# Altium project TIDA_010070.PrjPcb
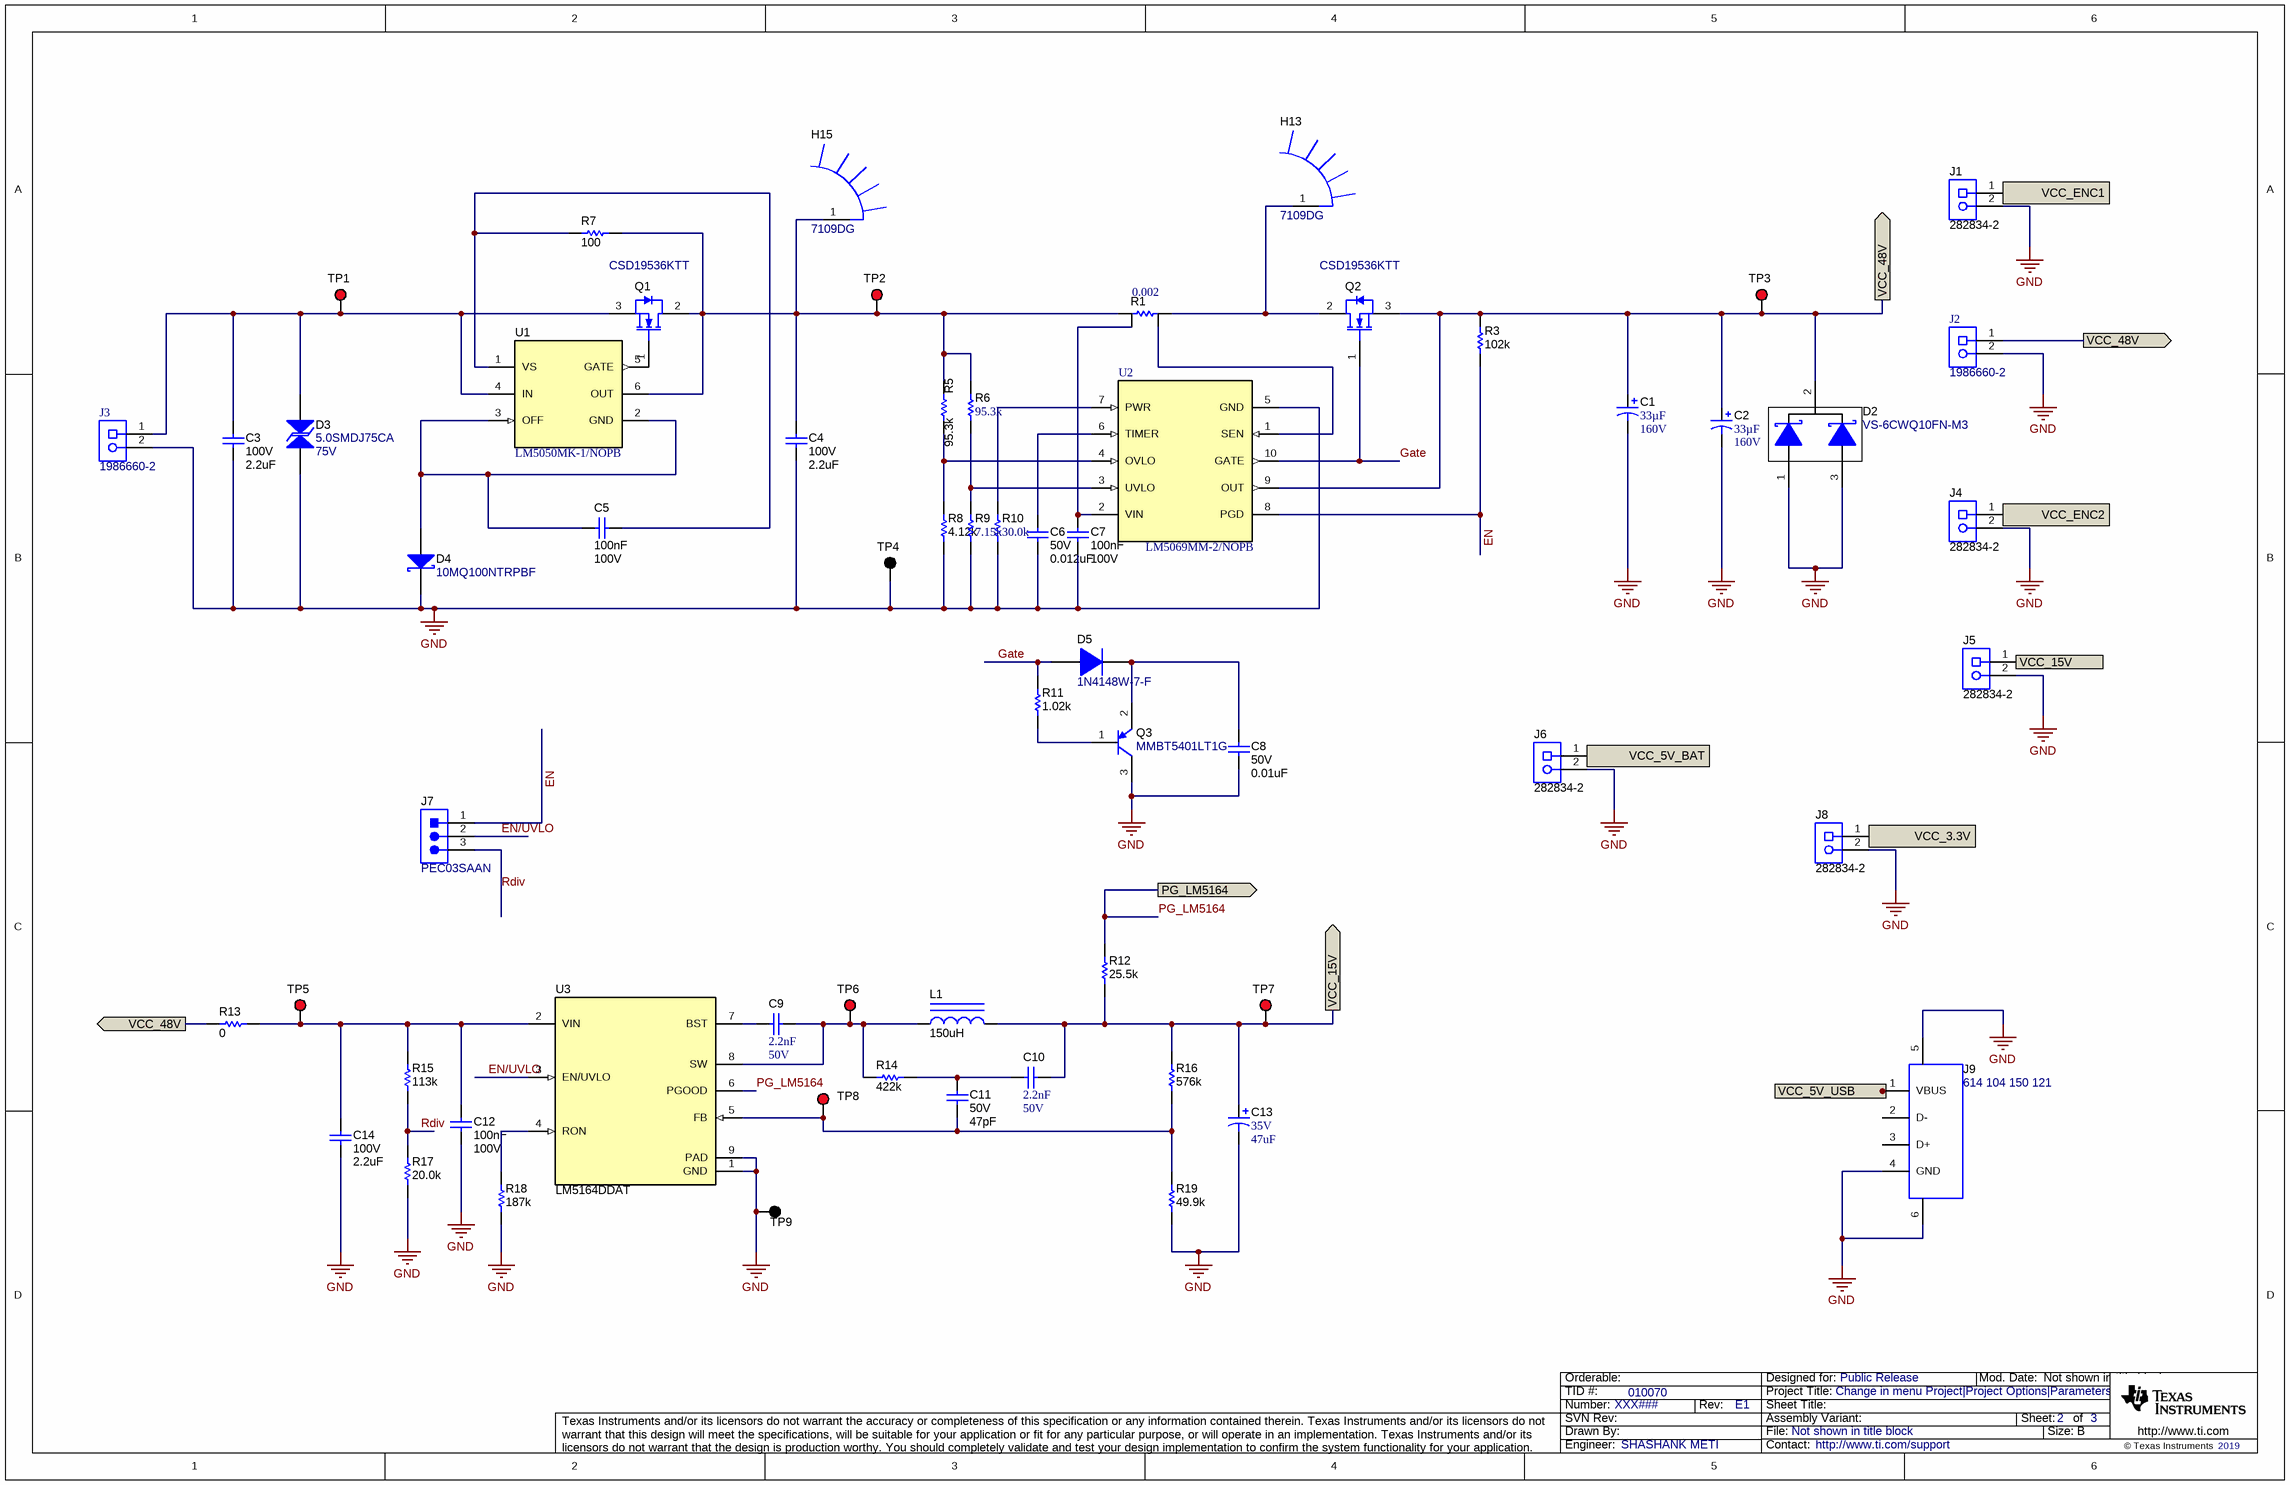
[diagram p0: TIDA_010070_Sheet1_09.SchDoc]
CopyrightYear: 2019; PCB_Layout: TESSOLVE; PCB_Rev: E1; PRJ_Customer: Public Release; PRJ_Engineer: SHASHANK METI; PRJ_Number: XXX###; PRJ_Title: Change in menu Project|Project Options|Parameters; SCH_Rev: E1; TechSupport: http://www.ti.com/support; TID: 010070
3 sheets, 149 parts. Net scope: flat (ports and power ports of the same name join across sheets).
Sheets:
  TIDA_010070_Sheet1_09.SchDoc
  TIDA_010070_Sheet2_09.SchDoc
  TIDA_010070_Hardware.SchDoc

## Sheet TIDA_010070_Sheet1_09.SchDoc
size 431 x 279 mm; Date: Not shown in title block; ApprovedBy: Not shown in title block; CheckedBy: Not shown in title block; Author: Not shown in title block; CompanyName: Not shown in title block; Engineer: Not shown in title block; Organization: Not shown in title block; Address1: Not shown in title block; Address2: Not shown in title block; Address3: Not shown in title block; Address4: Not shown in title block; DocumentNumber: 2; Revision: Use project parameter SCH_Rev; SheetNumber: 2; SheetTotal: 3; PageSetup: Record=PageOptions¦CenterHorizontal=True¦CenterVertical=True¦PrintScale=1.00¦XCorrection=1.00¦YCorrection=1.00¦PrintKind=0¦BorderSize=5000000¦LeftOffset=0¦BottomOffset=0¦Orientation=2¦PaperLength=1000¦PaperWidth=1000¦Scale=100¦PaperSource=15¦PrintQuality=600¦MediaType=1¦DitherType=10¦PaperKind=Letter¦PrintScaleMode=1

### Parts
C1  ValueDisplayed: 33µF  VDC_V: 160V  [EB_H16]  (hidden comment: EEV-EB2C330SQ)
C2  ValueDisplayed: 33µF  VDC_V: 160V  [EB_H16]  (hidden comment: EEV-EB2C330SQ)
C3  VDC_V: 100V  ValueDisplayed: 2.2uF  [1210_250]  (hidden comment: CGA6N3X7R2A225K230AB)
C4  VDC_V: 100V  ValueDisplayed: 2.2uF  [1210_250]  (hidden comment: CGA6N3X7R2A225K230AB)
C5  Cap_F: 100nF  VDC_V: 100V  [0603]  (hidden comment: HMK107B7104KAHT)
C6  VDC_V: 50V  ValueDisplayed: 0.012uF  [1206]  (hidden comment: CC1206KRX7R9BB123)
C7  Cap_F: 100nF  VDC_V: 100V  [0603]  (hidden comment: HMK107B7104KAHT)
C8  VDC_V: 50V  ValueDisplayed: 0.01uF  [1206]  (hidden comment: 12065C103KAT2A)
C9  Cap_F: 2.2nF  VDC_V: 50V  [0603]  (hidden comment: C0603C222K5RACTU)
C10  Cap_F: 2.2nF  VDC_V: 50V  [0603]  (hidden comment: C0603C222K5RACTU)
C11  VDC_V: 50V  ValueDisplayed: 47pF  [0805_HV]  (hidden comment: C0805C470J5GACTU)
C12  Cap_F: 100nF  VDC_V: 100V  [0603]  (hidden comment: HMK107B7104KAHT)
C13  VDC_V: 35V  ValueDisplayed: 47uF  [SM_RADIAL_D]  (hidden comment: EEE-FK1V470P)
C14  VDC_V: 100V  ValueDisplayed: 2.2uF  [1210_250]  (hidden comment: CGA6N3X7R2A225K230AB)
D2  VS-6CWQ10FN-M3  [DPAK]
D3  5.0SMDJ75CA  value 75V  [SMC_Bi]
D4  10MQ100NTRPBF  [SMA]
D5  1N4148W-7-F  [SOD-123]
H13  7109DG  [Aavid_7109DG]
H15  7109DG  [Aavid_7109DG]
J1  282834-2  [TEC_282834-2]
J2  1986660-2  [TE-1986660-2]
J3  1986660-2  [TE-1986660-2]
J4  282834-2  [TEC_282834-2]
J5  282834-2  [TEC_282834-2]
J6  282834-2  [TEC_282834-2]
J7  PEC03SAAN  [CONN_PEC03SAAN]
J8  282834-2  [TEC_282834-2]
J9  614 104 150 121  [WURTH_614104150121]
L1  ValueDisplayed: 150uH  [MSS1210]  (hidden comment: MSS1210-154KE)
Q1  CSD19536KTT  [KTT0002A]
Q2  CSD19536KTT  [KTT0002A]
Q3  MMBT5401LT1G  [SOT-23]
R1  ValueDisplayed: 0.002  [WSL4026_310]  (hidden comment: WSL40262L000FEB)
R3  ValueDisplayed: 102k  [0603]  (hidden comment: CRCW0603102KFKEA)
R5  value 95.3k  [0603_HV]  (hidden comment: CRCW060395K3FKEA)
R6  ValueDisplayed: 95.3k  [0603]  (hidden comment: RT0603BRD0795K3L)
R7  value 100  [0603]  (hidden comment: CRCW0603100RFKEA)
R8  ValueDisplayed: 4.12k  [0603]  (hidden comment: CRCW06034K12FKEA)
R9  ValueDisplayed: 7.15k  [0603]  (hidden comment: RG1608P-7151-B-T5)
R10  ValueDisplayed: 30.0k  [0603]  (hidden comment: RG1608P-303-B-T5)
R11  ValueDisplayed: 1.02k  [1206]  (hidden comment: RC1206FR-071K02L)
R12  ValueDisplayed: 25.5k  [0805_HV]  (hidden comment: CRCW080525K5FKEA)
R13  ValueDisplayed: 0  [5106]  (hidden comment: 5106)
R14  ValueDisplayed: 422k  [0805_HV]  (hidden comment: ERJ-6ENF4223V)
R15  ValueDisplayed: 113k  [0603]  (hidden comment: CRCW0603113KFKEA)
R16  ValueDisplayed: 576k  [0603]  (hidden comment: RC0603FR-07576KL)
R17  ValueDisplayed: 20.0k  [0603]  (hidden comment: CRCW060320K0FKEA)
R18  ValueDisplayed: 187k  [0603]  (hidden comment: CRCW0603187KFKEA)
R19  ValueDisplayed: 49.9k  [0603]  (hidden comment: RC0603FR-0749K9L)
TP1  5000  [Keystone5000]  (value not drawn)
TP2  5000  [Keystone5000]  (value not drawn)
TP3  5000  [Keystone5000]  (value not drawn)
TP4  5001  [Keystone5001]  (value not drawn)
TP5  5000  [Keystone5000]  (value not drawn)
TP6  5000  [Keystone5000]  (value not drawn)
TP7  5000  [Keystone5000]  (value not drawn)
TP8  5000  [Keystone5000]  (value not drawn)
TP9  5001  [Keystone5001]  (value not drawn)
U1  LM5050MK-1/NOPB  [DDC0006A_N]
U2  LM5069MM-2/NOPB  [DGS0010A_N]
U3  LM5164DDAT  [DDA0008E_N]

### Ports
PG_LM5164 (out), VCC_3.3V (in), VCC_5V_BAT (in), VCC_5V_USB (in), VCC_15V (out), VCC_48V (out), VCC_ENC1 (in), VCC_ENC2 (in)

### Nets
GND: C1.2(-) C2.2(-) C3.1 C4.1 C6.1 C7.2 C8.1 C12.2 C13.2(-) C14.1 D2.1(A) D2.3(A) D3.1 D4.1(K) J1.2 J2.2 J3.2 J4.2 J5.2 J6.2 J8.2 J9.4(GND) J9.5(Shield) J9.6(Shield) Q3.3(C) R8.2 R9.2 R10.1 R17.2 R18.2 R19.2 TP4.1 TP9.1 U2.5(GND) U3.1(GND) U3.9(PAD)
V_5VBAT: J6.1 ; port VCC_5V_BAT
V_P: J8.1 ; port VCC_3.3V
EN: J7.1 R3.2 U2.8(PGD)
EN/UVLO: J7.2 U3.3(EN/UVLO)
Gate: D5.2(A) Q2.1(G) R11.1 U2.10(GATE)
PG_LM5164: R12.1 U3.6(PGOOD) ; port PG_LM5164
Rdiv: J7.3 R15.2 R17.1
VCC_15V: C10.1 C13.1(+) J5.1 L1.2 R12.2 R16.1 TP7.1 ; port VCC_15V
VCC_48V: C1.1(+) C2.1(+) D2.2(K) J2.1 Q2.3(S) R3.1 R13.1 TP3.1 U2.9(OUT) ; port VCC_48V
VCC_ENC1: J1.1 ; port VCC_ENC1
VCC_ENC2: J4.1 ; port VCC_ENC2
NetC3_2: C3.2 D3.2 J3.1 Q1.3(S) TP1.1 U1.4(IN)
NetC4_2: C4.2 H15.1 Q1.2(D) R1.2 R5.2 R6.2 R7.1 TP2.1 U1.6(OUT)
NetC5_1: C5.1 R7.2 U1.1(VS)
NetC5_2: C5.2 D4.2(A) U1.2(GND) U1.3(OFF)
NetC6_2: C6.2 U2.6(TIMER)
NetC7_1: C7.1 R1.4 U2.2(VIN)
NetC8_2: C8.2 D5.1(K) Q3.2(E)
NetC9_1: C9.1 L1.1 R14.1 TP6.1 U3.8(SW)
NetC9_2: C9.2 U3.7(BST)
NetC10_2: C10.2 C11.2 R14.2
NetC11_1: C11.1 R16.2 R19.1 TP8.1 U3.5(FB)
NetC12_1: C12.1 C14.2 R13.2 R15.1 TP5.1 U3.2(VIN)
NetH13_1: H13.1 Q2.2(D) R1.1
NetQ1_1: Q1.1(G) U1.5(GATE)
NetQ3_1: Q3.1(B) R11.2
NetR1_3: R1.3 U2.1(SEN)
NetR5_1: R5.1 R8.1 U2.4(OVLO)
NetR6_1: R6.1 R9.1 U2.3(UVLO)
NetR10_2: R10.2 U2.7(PWR)
NetR18_1: R18.1 U3.4(RON)

Not connected (* = marked no-connect by the designer): J9 1(VBUS) 2(D-) 3(D+)

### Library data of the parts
C1 C2 = CMP-0860221-1: CAP, AL, 33 µF, 160 V, +/- 20%, SMD; Manufacturer: Panasonic; SizeZ_mm: 13.5; Cap_Case: 12.5x16.5mm; CompType: Capacitor; Value: 33uF; U/M: EA; TaMax_C: 105°C; TaMin_C: -55°C; SizeAreaWB_mm2: 263.5; Polarized: Y; AEC Qualified: N; IRMS_A: 4.7dA; AEC Category: Q200; SizeArea_mm2: 202.5; SizeX_mm: 15
C3 C4 C14 = CMP-0009152-2: CAP, CERM, 2.2 uF, 100 V, +/- 10%, X7R, AEC-Q200 Grade 1,; Manufacturer: TDK; TaMin_C: -55°C; ESR_ohm: 1.73m; Polarized: N; SizeAreaWB_mm2: 14.7; Value1: 0.00173 ohm; U/M: EA; Value: 2.2uF; TaMax_C: 125°C; SizeZ_mm: 2.5; SizeX_mm: 3.2; SizeArea_mm2: 8; AEC Qualified: Y; Cap_F: 2.2µF; IRMS_A: 5.59317A; AEC Grade: 1; AEC Category: Q200
C5 C7 C12 = CMP-0081011-1: CAP, CERM, 0.1 µF, 100 V,+/- 10%, X7R, AEC-Q200 Grade 1, 0603; Manufacturer: Taiyo Yuden; SizeAreaWB_mm2: 4.68; SizeArea_mm2: 1.28; AEC Qualified: Y; AEC Category: Q200; Value: 0.1uF; TaMax_C: 125°C; SizeZ_mm: 1; Polarized: N; TaMin_C: -55°C; SizeY_mm: 0.8; U/M: EA; SizeX_mm: 1.6; ValueDisplayed: 0.1µF
C6 = CMP-0008741-2: CAP, CERM, 0.012 uF, 50 V, +/- 10%, X7R, 1206; Manufacturer: Yageo America; TaMin_C: -55°C; Polarized: N; SizeAreaWB_mm2: 10.92; Value1: Unknown; U/M: EA; TaMax_C: 125°C; SizeZ_mm: 1.35; SizeX_mm: 3.2; SizeY_mm: 1.6; SizeArea_mm2: 5.12; Cap_F: 12nF; AEC Category: Q200
C8 = CMP-0008531-2: CAP, CERM, 0.01 uF, 50 V, +/- 10%, X7R, 1206; Manufacturer: AVX; TaMin_C: -55°C; ESR_ohm: 0.119; Polarized: N; SizeAreaWB_mm2: 10.92; Value1: 0.119 ohm; U/M: EA; Value: 0.01uF; TaMax_C: 125°C; SizeZ_mm: 1.35; SizeX_mm: 3.2; SizeY_mm: 1.6; SizeArea_mm2: 5.12; Cap_F: 10nF; AEC Category: Q200
C9 C10 = CMP-0006898-4: CAP, CERM, 2200 pF, 50 V, +/- 10%, X7R, 0603; Manufacturer: Kemet; TaMin_C: -55°C; Polarized: N; SizeAreaWB_mm2: 4.68; Value1: Unknown; U/M: EA; Value: 2200pF; TaMax_C: 125°C; SizeZ_mm: 1; SizeX_mm: 1.6; SizeY_mm: 0.8; SizeArea_mm2: 1.28; AEC Category: Q200
C11 = CMP-0007793-2: CAP, CERM, 47 pF, 50 V, +/- 5%, C0G/NP0, 0805; Manufacturer: Kemet; TaMin_C: -55°C; ESR_ohm: 0.115; Polarized: N; SizeAreaWB_mm2: 6.75; Value1: 0.115 ohm; U/M: EA; Value: 47pF; TaMax_C: 125°C; SizeZ_mm: 1.45; SizeX_mm: 2; SizeY_mm: 1.25; Cap_Case: 0805; SizeArea_mm2: 2.5; IRMS_A: 505mA; AEC Category: Q200
C13 = CMP-0010730-1: CAP, AL, 47 uF, 35 V, +/- 20%, 0.36 ohm, AEC-Q200 Grade 2, SMD; Manufacturer: Panasonic; TaMin_C: -55°C; ESR_ohm: 3.6d; Polarized: Y; SizeAreaWB_mm2: 84.28; U/M: EA; Value: 47uF; TaMax_C: 105°C; SizeZ_mm: 5.4; SizeX_mm: 7.8; SizeY_mm: 6.6; Cap_Case: D; SizeArea_mm2: 51.48; CompType: Capacitor; Cap_F: 47µF; IRMS_A: 2.4dA; AEC Grade: 2; AEC Category: Q200
D2 = CMP-0028773-3: Diode, Schottky, 100 V, 3.5 A, DPAK; Manufacturer: Vishay-Semiconductor; SizeX_mm: 9.91; SizeY_mm: 6.54; Io_A: 3.5A; SizeZ_mm: 2.29; Value: 100V; Green_REACh: Incomplete; AEC Category: Q101; Value2: 0.96V; AEC Qualified: N; SizeArea_mm2: 64.8114; SizeAreaWB_mm2: 101.7114; Green_Lifecycle: Not Set; RJC_CperW: 4.7; Vf_V: 960mV; TJmax_C: 150°C
D3 = CMP-0085455-1: PartNumber: SMCJ26CA-TR; Manufacturer: STMicroelectronics; RJA_CperW: 90; AEC Qualified: N; Vc: 42.1V; Vbr_Min: 28.9V; SizeY_mm: 5.9; Ppk: 1.5kW; VRWM: 26V; SizeArea_mm2: 46.846; AEC Category: Q101; SizeAreaWB_mm2: 78.526; CompType: TVS; Ipp: 37A; SizeZ_mm: 2.62; SizeX_mm: 7.94
D4 = CMP-0028354-2: Diode, Schottky, 100 V, 1.5 A, SMA; Manufacturer: International Rectifier; Green_REACh: Incomplete; SizeAreaWB_mm2: 37.3428; TJmax_C: 150°C; SizeX_mm: 5.59; Value1: 1.5A; AEC Category: Q101; Vf_V: 680mV; Vr_V: 100V; SizeY_mm: 2.92; Green_Lifecycle: Not Set; Value: 100V; SizeArea_mm2: 16.3228; Value2: 0.68V; SizeZ_mm: 2.87
D5 = CMP-0029001-2: Diode, Ultrafast, 100 V, 0.15 A, SOD-123; Manufacturer: Diodes Inc.; SizeX_mm: 3.85; Value2: 1.25V; Green_REACh: Passed; TJmax_C: 150°C; AEC Category: Q101; SizeAreaWB_mm2: 13.095; Value: 100V; Green_Lifecycle: Active; SizeY_mm: 1.7; Value1: 0.15A; SizeArea_mm2: 6.545; Io_A: 150mA; SizeZ_mm: 1.35
H13 H15 = CMP-0004038-1: Surface mount heat sink for D2PAK; Manufacturer: Aavid
J1 J4-J6 J8 = CMP-0054974-1: Terminal Block, 2x1, 2.54mm, TH; Manufacturer: TE Connectivity; CNHeader: FALSE; Green_Lifecycle: Active; Green_REACh: Passed; CT: TRUE
J2 J3 = CMP-0085661-1: Terminal Block, 2 Pos, 10.16mm, TH; Manufacturer: TE Connectivity; Cert_UL: Y; Row_Count: 1; Voltage_V: 300V; Current_A: 65A; Pitch_mm: 10.16; Gender: Female
J7 = CMP-0002338-1: Header, 100mil, 3x1, Tin, TH; Manufacturer: Sullins Connector Solutions; CNHeader: TRUE; Current_A: 3A; Green_Lifecycle: Not Set; Shrouded: N; Gender: Male; Green_REACh: Incomplete; Voltage_V: 1.8kV; Row_Count: 1; Pitch_mm: 2.54; CT: FALSE; Cert_UL: Y
J9 = CMP-0054815-1: Connector, Receptacle, USB Type A, R/A, Bottom Mount TH; Manufacturer: Wurth Elektronik; Gender: Female; CT: TRUE; CNHeader: FALSE
L1 = CMP-0061864-2: Inductor, Shielded, Ferrite, 150 uH, 2.5 A, 0.176 ohm, SMD; Manufacturer: Coilcraft; Isat: 3.4A @ 30% inductance drop; Irms: 2.5A @ 40C rise; Green_Lifecycle: Not Set; SizeAreaWB_mm2: 204.49; DCR_ohm: 0.176; Green_REACh: Incomplete; Value: 150uH; Imax_A: 2.5A; SizeZ_mm: 10; SizeX_mm: 12.3; SizeArea_mm2: 151.29; Ind_H: 150µH; AEC Category: Q200
Q1 Q2 = CMP-0000966-3: MOSFET, N-CH, 100 V, 200 A, KTT0002A (TO-263-2); Alternate Manufacturer: None; Manufacturer: Texas Instruments; SizeZ_mm: 4.7; ChType: N; Value2: 118 nC; VdsMax_V: 100V; SizeX_mm: 14.3; SizeY_mm: 10.16; Vgs_V: 20V; QgTyp_nC: 118; Value: 100V; SizeArea_mm2: 145.288; AEC Category: Q101; IdsMax_A: 200A; SizeAreaWB_mm2: 198.208
Q3 = CMP-0000333-2: Transistor, PNP, 150 V, 0.5 A, SOT-23; Manufacturer: ON Semiconductor; TaMax_C: 150°C; Value2: 240; Value1: 0.5 A; Vcesat1_V: 500mV; SizeX_mm: 2.5; SizeY_mm: 3; TaMin_C: -55°C; IcRated_A: 500mA; CompType: BJT; SizeZ_mm: 1.1; Value: 150 V; SizeArea_mm2: 7.5; NPN: 0; Vceo_V: 150V; PNP: 1; AEC Category: Q101; SizeAreaWB_mm2: 14; U/M: EA
R1 = CMP-0015295-2: RES, 0.002, 1%, 3 W, AEC-Q200 Grade 0, 4026; Manufacturer: Vishay-Dale; Power_W: 3W; TempCo: 75 ppm/C; Value_Code: 2L000; U/M: EA; Value: 0.002; Res_ohm: 2m; CompType: Resistor; AEC Qualified: Y; AEC Grade: 0; AEC Category: Q200
R3 = CMP-0021992-4: RES, 102 k, 1%, 0.1 W, AEC-Q200 Grade 0, 0603; Manufacturer: Vishay-Dale; Power_W: 100mW; TempCo: 100 ppm/C; Value: 102k; EIA_Code: E96; SizeX_mm: 1.6; SizeY_mm: 0.8; SizeZ_mm: 1; Value2: 0.1W; SizeArea_mm2: 1.28; AEC Qualified: Y; VDC_V: 75V; AEC Category: Q200; AEC Grade: 0
R5 = CRCW060395K3FKEA: RES, 95.3k ohm, 1%, 0.1W, 0603; Manufacturer: Vishay-Dale; CompType: Resistor; Res_ohm: 95300; Value_Code: 95k3; Tolerance_%: 1; Power_W: 0.1; VDC_V: 75; TempCo: 100 ppm/C; EIA_Code: E96; U/M: EA
R6 = CMP-0024540-3: RES, 95.3 k, 0.1%, 0.1 W, 0603; Manufacturer: Yageo America; Power_W: 100mW; TempCo: 25 ppm/C; Value_Code: 95k3; U/M: EA; Value: 95.3k; EIA_Code: E192; SizeX_mm: 1.6; SizeY_mm: 0.8; SizeZ_mm: 1; Value2: 0.1W; SizeArea_mm2: 1.28; VDC_V: 75V; AEC Category: Q200
R7 = CRCW0603100RFKEA: RES, 100 ohm, 1%, 0.1W, 0603; Manufacturer: Vishay-Dale; CompType: Resistor; Value_Code: 100R; Tolerance_%: 1; Power_W: 0.1; VDC_V: 75; TempCo: 100 ppm/C; EIA_Code: E96; U/M: EA
R8 = CMP-0022450-4: RES, 4.12 k, 1%, 0.1 W, AEC-Q200 Grade 0, 0603; Manufacturer: Vishay-Dale; Power_W: 100mW; TempCo: 100 ppm/C; Value_Code: 4k12; Value: 4.12k; EIA_Code: E96; SizeX_mm: 1.6; SizeY_mm: 0.8; SizeZ_mm: 1; Value2: 0.1W; SizeArea_mm2: 1.28; AEC Qualified: Y; VDC_V: 75V; AEC Category: Q200; AEC Grade: 0
R9 = CMP-0023594-3: RES, 7.15 k, 0.1%, 0.1 W, 0603; Manufacturer: Susumu Co Ltd; Power_W: 100mW; TempCo: 25 ppm/C; Value_Code: 7k15; U/M: EA; Value: 7.15k; EIA_Code: E192; SizeX_mm: 1.6; SizeY_mm: 0.8; SizeZ_mm: 1; Value2: 0.1W; SizeArea_mm2: 1.28; VDC_V: 75V; AEC Category: Q200
R10 = CMP-0023508-3: RES, 30.0 k, 0.1%, 0.1 W, 0603; Manufacturer: Susumu Co Ltd; Power_W: 100mW; TempCo: 25 ppm/C; Value_Code: 30k0; U/M: EA; Value: 30.0k; Res_ohm: 30k; SizeX_mm: 1.6; SizeY_mm: 0.8; SizeZ_mm: 1; Value2: 0.1W; SizeArea_mm2: 1.28; VDC_V: 75V; AEC Category: Q200
R11 = CMP-0017964-2: RES, 1.02 k, 1%, 0.25 W, 1206; Manufacturer: Yageo America; Power_W: 250mW; TempCo: 100 ppm/C; Value_Code: 1k02; U/M: EA; Value: 1.02k; EIA_Code: E96; SizeX_mm: 3.2; SizeY_mm: 1.6; SizeZ_mm: 1.35; Value2: 0.25W; SizeArea_mm2: 5.12; VDC_V: 200V; AEC Category: Q200
R12 = CMP-0021080-3: RES, 25.5 k, 1%, 0.125 W, AEC-Q200 Grade 0, 0805; Manufacturer: Vishay-Dale; Power_W: 125mW; TempCo: 100 ppm/C; Value_Code: 25k5; Value: 25.5k; EIA_Code: E96; SizeX_mm: 2; SizeY_mm: 1.25; SizeZ_mm: 1.45; Value2: 0.125W; SizeArea_mm2: 2.5; AEC Qualified: Y; VDC_V: 150V; AEC Category: Q200; AEC Grade: 0
R13 = CMP-0020833-2: RES, 0, 1%, 0.5 W, 0805; Manufacturer: Keystone; Power_W: 500mW; TempCo: ppm/C; U/M: EA; Value: 0; SizeX_mm: 2; SizeY_mm: 1.25; SizeZ_mm: 0.84; Value2: 0.5W; SizeArea_mm2: 2.5; AEC Qualified: N; AEC Category: Q200
R14 = CMP-0021713-3: RES, 422 k, 1%, 0.125 W, AEC-Q200 Grade 0, 0805; Manufacturer: Panasonic; Power_W: 125mW; TempCo: 100 ppm/C; Value: 422k; EIA_Code: E96; SizeX_mm: 2; SizeY_mm: 1.25; SizeZ_mm: 1.45; Value2: 0.125W; SizeArea_mm2: 2.5; AEC Qualified: Y; AEC Category: Q200; AEC Grade: 0; SizeAreaWB_mm2: 6.75
R15 = CMP-0022010-4: RES, 113 k, 1%, 0.1 W, AEC-Q200 Grade 0, 0603; Manufacturer: Vishay-Dale; Power_W: 100mW; TempCo: 100 ppm/C; Value: 113k; EIA_Code: E96; SizeX_mm: 1.6; SizeY_mm: 0.8; SizeZ_mm: 1; Value2: 0.1W; SizeArea_mm2: 1.28; AEC Qualified: Y; VDC_V: 75V; AEC Category: Q200; AEC Grade: 0
R16 = CMP-0023189-4: RES, 576 k, 1%, 0.1 W, 0603; Manufacturer: Yageo; Power_W: 100mW; TempCo: 100 ppm/C; Value: 576k; EIA_Code: E96; SizeX_mm: 1.6; SizeY_mm: 0.8; SizeZ_mm: 1; Value2: 0.1W; SizeArea_mm2: 1.28; AEC Qualified: N; VDC_V: 75V; AEC Category: Q200; SizeAreaWB_mm2: 4.68
R17 = CMP-0022204-4: RES, 20.0 k, 1%, 0.1 W, AEC-Q200 Grade 0, 0603; Manufacturer: Vishay-Dale; Power_W: 100mW; TempCo: 100 ppm/C; Value_Code: 20k0; Value: 20.0k; EIA_Code: E96; Res_ohm: 20k; SizeX_mm: 1.6; SizeY_mm: 0.8; SizeZ_mm: 1; Value2: 0.1W; SizeArea_mm2: 1.28; AEC Qualified: Y; VDC_V: 75V; AEC Category: Q200; AEC Grade: 0
R18 = CMP-0022095-4: RES, 187 k, 1%, 0.1 W, AEC-Q200 Grade 0, 0603; Manufacturer: Vishay-Dale; Power_W: 100mW; TempCo: 100 ppm/C; Value: 187k; EIA_Code: E96; SizeX_mm: 1.6; SizeY_mm: 0.8; SizeZ_mm: 1; Value2: 0.1W; SizeArea_mm2: 1.28; AEC Qualified: Y; VDC_V: 75V; AEC Category: Q200; AEC Grade: 0
R19 = CMP-0023142-5: RES, 49.9 k, 1%, 0.1 W, 0603; Manufacturer: Yageo; Power_W: 100mW; TempCo: 100 ppm/C; Value_Code: 49k9; Value: 49.9k; EIA_Code: E96; SizeX_mm: 1.6; SizeY_mm: 0.8; SizeZ_mm: 1; Value2: 0.1W; SizeArea_mm2: 1.28; AEC Qualified: N; VDC_V: 75V; AEC Category: Q200; SizeAreaWB_mm2: 4.68
TP1-TP3 TP5-TP8 = CMP-0055137-1: Test Point, Miniature, Red, TH; Manufacturer: Keystone; CNHeader: FALSE; Green_Lifecycle: Active; Green_REACh: Passed; ContactFinish: Silver; CT: TRUE
TP4 TP9 = CMP-0055138-1: Test Point, Miniature, Black, TH; Manufacturer: Keystone; CNHeader: FALSE; Green_Lifecycle: Active; Green_REACh: Passed; ContactFinish: Silver; CT: TRUE
U1 = CMP-0066129-2: High Side OR-ing FET Controller, DDC0006A (SOT-23-T-6); Manufacturer: Texas Instruments; SizeZ_mm: 0.87; SizeX_mm: 1.65; SizeY_mm: 2.95; SizeArea_mm2: 4.8675; CompType: IC; U/M: EA; SizeAreaWB_mm2: 10.4675
U2 = CMP-0071871-1: Positive High Voltage Hot Swap / Inrush Current Controller with Power Limiting, 10-pin MSOP, Pb-Free; Manufacturer: Texas Instruments; PackageTopMarking: ZXTT*SNBB; CompType: MiscPower; PowerWise: N
U3 = CMP-0080798-1: 100-V Low IQ Synchronous Buck Regulator, DDA0008E (SOIC-8); Alternate Manufacturer: Texas Instruments; SizeAreaWB_mm2: 57.4; SizeZ_mm: 1.7; SizeX_mm: 5; SizeY_mm: 6.2; SizeArea_mm2: 31; CompType: IC; AEC Qualified: N; AEC Category: Q200

## Sheet TIDA_010070_Sheet2_09.SchDoc
size 431 x 279 mm; Date: Not shown in title block; ApprovedBy: Not shown in title block; CheckedBy: Not shown in title block; Author: Not shown in title block; CompanyName: Not shown in title block; Engineer: Not shown in title block; Organization: Not shown in title block; Address1: Not shown in title block; Address2: Not shown in title block; Address3: Not shown in title block; Address4: Not shown in title block; DocumentNumber: 2; Revision: Use project parameter SCH_Rev; SheetNumber: 2; SheetTotal: 3; PageSetup: Record=PageOptions¦CenterHorizontal=True¦CenterVertical=True¦PrintScale=1.00¦XCorrection=1.00¦YCorrection=1.00¦PrintKind=0¦BorderSize=5000000¦LeftOffset=0¦BottomOffset=0¦Orientation=2¦PaperLength=1000¦PaperWidth=1000¦Scale=100¦PaperSource=15¦PrintQuality=600¦MediaType=1¦DitherType=10¦PaperKind=Letter¦PrintScaleMode=1
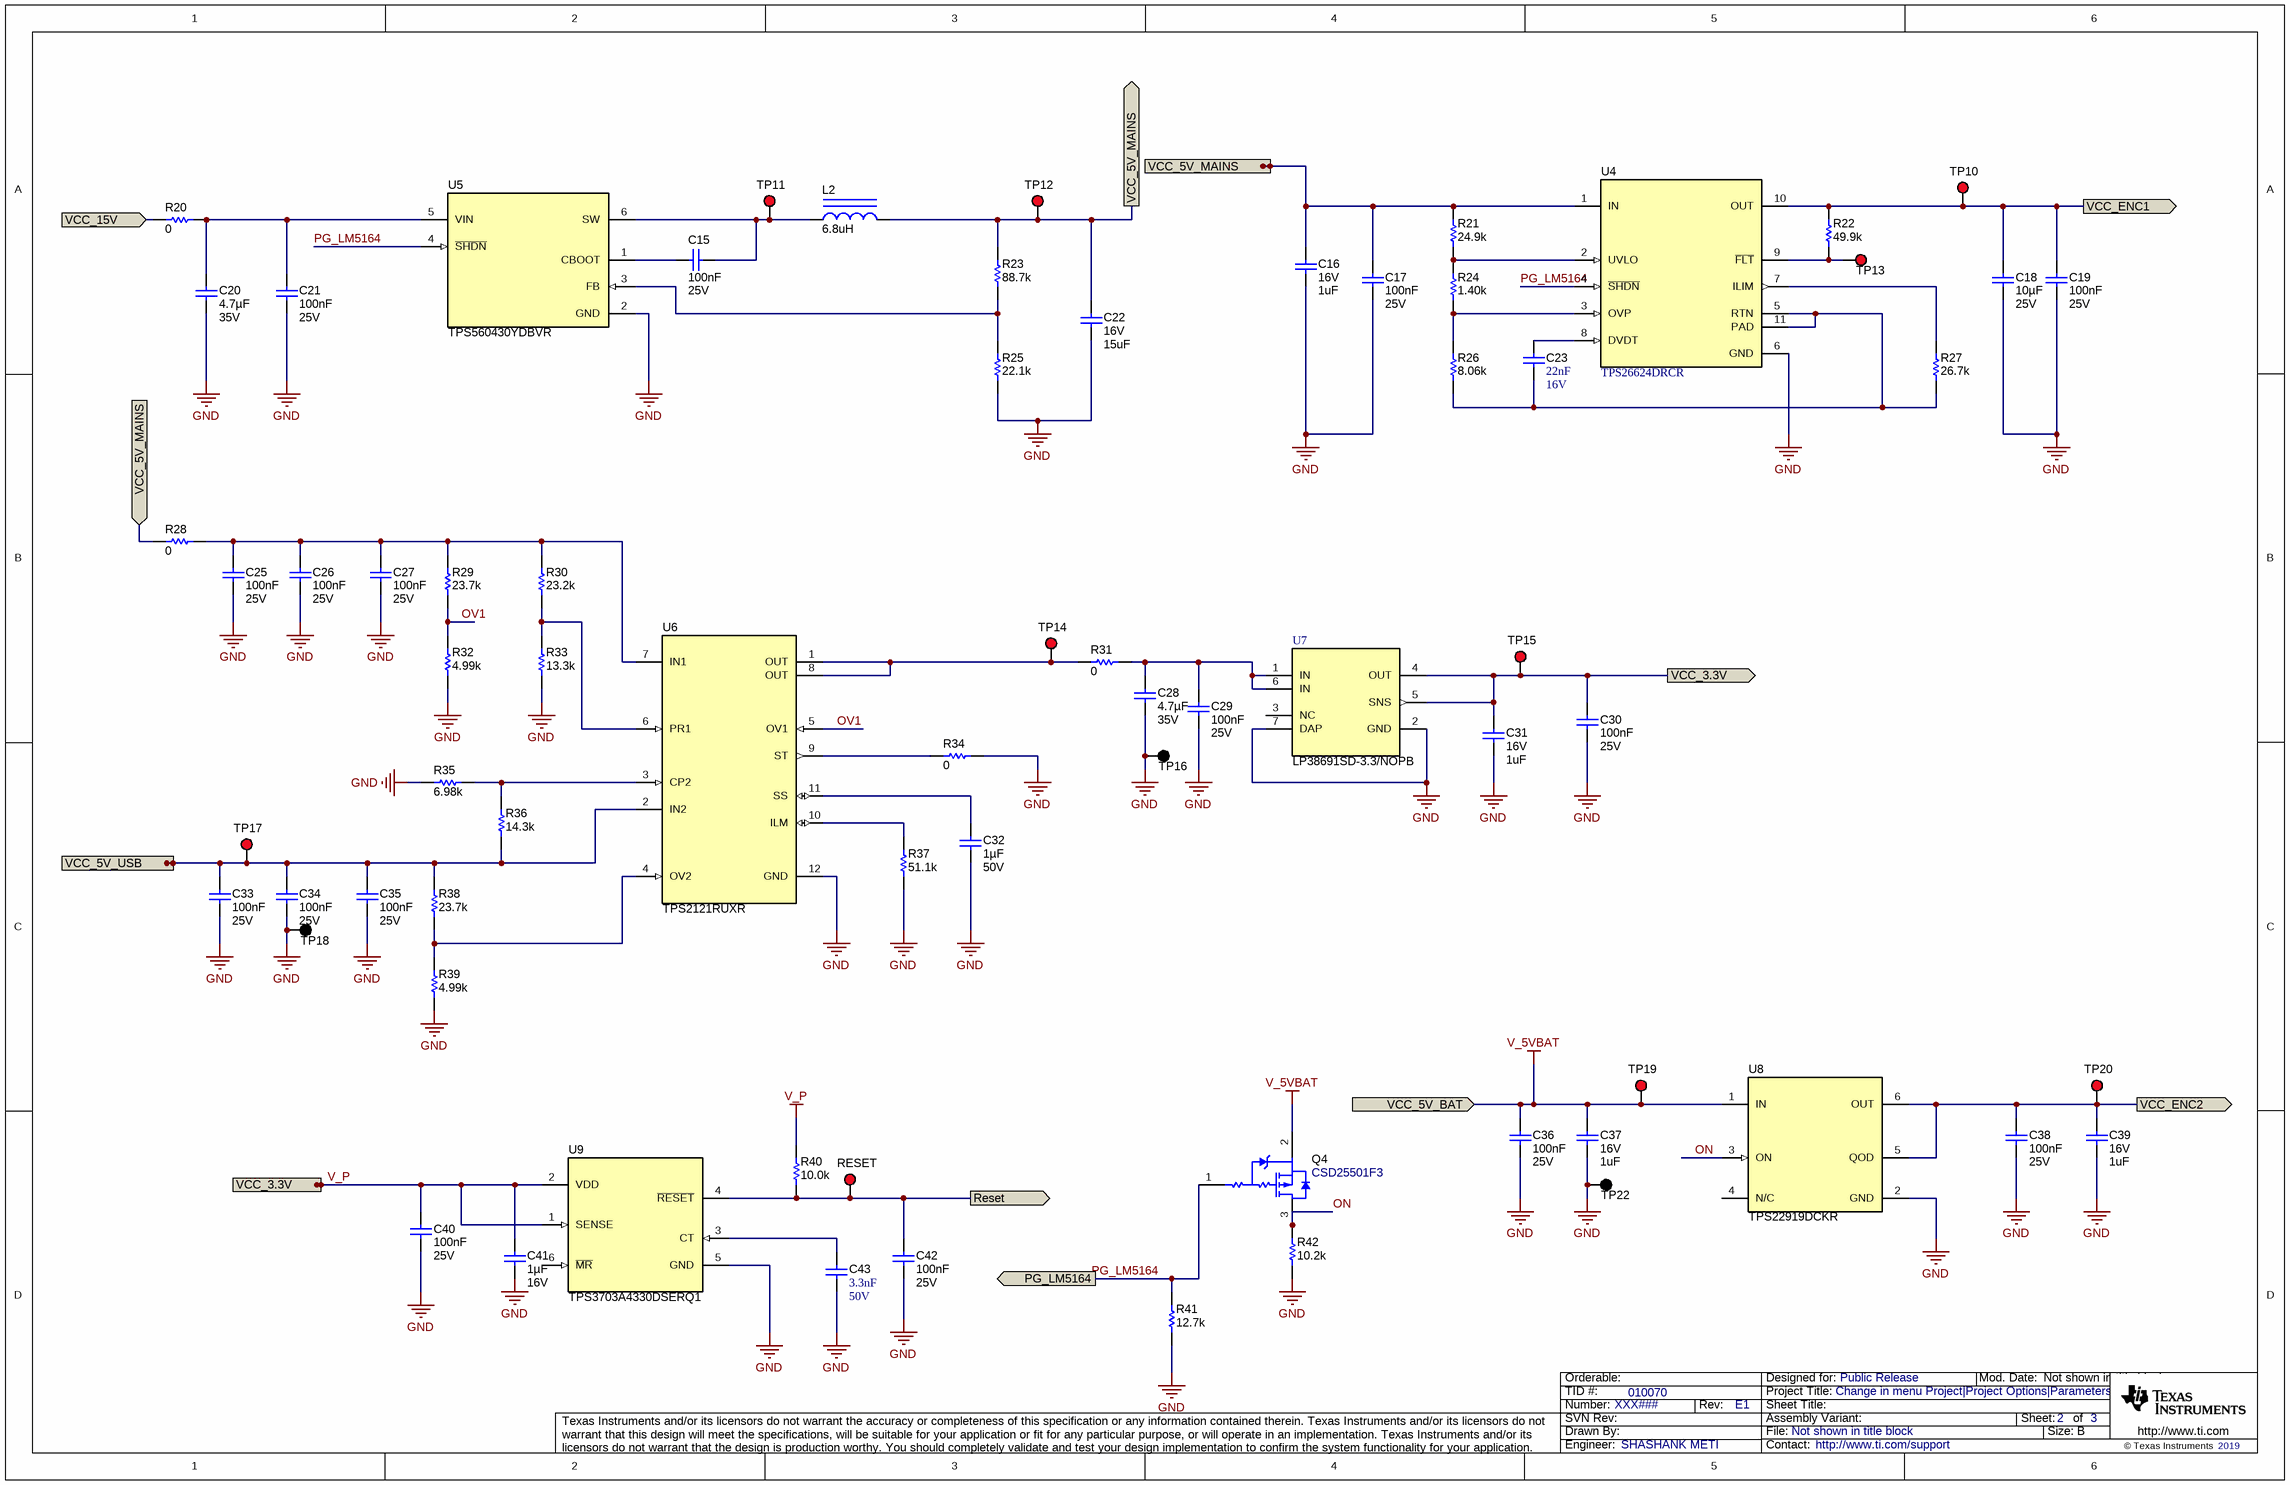
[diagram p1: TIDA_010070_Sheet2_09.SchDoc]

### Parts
C15  Cap_F: 100nF  VDC_V: 25V  [0603]  (hidden comment: 06033C104KAT2A)
C16  VDC_V: 16V  ValueDisplayed: 1uF  [0805_HV]  (hidden comment: C2012X8R1C105K125AB)
C17  Cap_F: 100nF  VDC_V: 25V  [0603]  (hidden comment: 06033C104KAT2A)
C18  Cap_F: 10µF  VDC_V: 25V  [0805_HV]  (hidden comment: GRM21BZ71E106KE15L)
C19  Cap_F: 100nF  VDC_V: 25V  [0603]  (hidden comment: 06033C104KAT2A)
C20  Cap_F: 4.7µF  VDC_V: 35V  [0805_HV]  (hidden comment: C2012X7R1V475K125AC)
C21  Cap_F: 100nF  VDC_V: 25V  [0603]  (hidden comment: 06033C104KAT2A)
C22  VDC_V: 16V  ValueDisplayed: 15uF  [1210_280]  (hidden comment: C3225X5R1C156M250AA)
C23  Cap_F: 22nF  VDC_V: 16V  [0603]  (hidden comment: C0603C223K4RACTU)
C25  Cap_F: 100nF  VDC_V: 25V  [0603]  (hidden comment: 06033C104KAT2A)
C26  Cap_F: 100nF  VDC_V: 25V  [0603]  (hidden comment: 06033C104KAT2A)
C27  Cap_F: 100nF  VDC_V: 25V  [0603]  (hidden comment: 06033C104KAT2A)
C28  Cap_F: 4.7µF  VDC_V: 35V  [0805_HV]  (hidden comment: C2012X7R1V475K125AC)
C29  Cap_F: 100nF  VDC_V: 25V  [0603]  (hidden comment: 06033C104KAT2A)
C30  Cap_F: 100nF  VDC_V: 25V  [0603]  (hidden comment: 06033C104KAT2A)
C31  VDC_V: 16V  ValueDisplayed: 1uF  [0805_HV]  (hidden comment: C2012X8R1C105K125AB)
C32  Cap_F: 1µF  VDC_V: 50V  [0805_HV]  (hidden comment: C0805C105K5RACTU)
C33  Cap_F: 100nF  VDC_V: 25V  [0603]  (hidden comment: 06033C104KAT2A)
C34  Cap_F: 100nF  VDC_V: 25V  [0603]  (hidden comment: 06033C104KAT2A)
C35  Cap_F: 100nF  VDC_V: 25V  [0603]  (hidden comment: 06033C104KAT2A)
C36  Cap_F: 100nF  VDC_V: 25V  [0603]  (hidden comment: 06033C104KAT2A)
C37  VDC_V: 16V  ValueDisplayed: 1uF  [0805_HV]  (hidden comment: C2012X8R1C105K125AB)
C38  Cap_F: 100nF  VDC_V: 25V  [0603]  (hidden comment: 06033C104KAT2A)
C39  VDC_V: 16V  ValueDisplayed: 1uF  [0805_HV]  (hidden comment: C2012X8R1C105K125AB)
C40  Cap_F: 100nF  VDC_V: 25V  [0603]  (hidden comment: 06033C104KAT2A)
C41  Cap_F: 1µF  VDC_V: 16V  [0603]  (hidden comment: GCM188R71C105KA64D)
C42  Cap_F: 100nF  VDC_V: 25V  [0603]  (hidden comment: 06033C104KAT2A)
C43  Cap_F: 3.3nF  VDC_V: 50V  [0603]  (hidden comment: C0603C332K5RACTU)
L2  ValueDisplayed: 6.8uH  [ME3220]  (hidden comment: ME3220-682MLB)
Q4  CSD25501F3  [YJN0003A]
R20  ValueDisplayed: 0  [5106]  (hidden comment: 5106)
R21  ValueDisplayed: 24.9k  [0603]  (hidden comment: CRCW060324K9FKEA)
R22  ValueDisplayed: 49.9k  [0603]  (hidden comment: CRCW060349K9FKEA)
R23  ValueDisplayed: 88.7k  [0603]  (hidden comment: CRCW060388K7FKEA)
R24  ValueDisplayed: 1.40k  [0603]  (hidden comment: CRCW06031K40FKEA)
R25  ValueDisplayed: 22.1k  [0603]  (hidden comment: CRCW060322K1FKEA)
R26  ValueDisplayed: 8.06k  [0603]  (hidden comment: CRCW06038K06FKEA)
R27  ValueDisplayed: 26.7k  [0603]  (hidden comment: CRCW060326K7FKEA)
R28  ValueDisplayed: 0  [5106]  (hidden comment: 5106)
R29  ValueDisplayed: 23.7k  [0603]  (hidden comment: CRCW060323K7FKEA)
R30  ValueDisplayed: 23.2k  [0603]  (hidden comment: CRCW060323K2FKEA)
R31  ValueDisplayed: 0  [5106]  (hidden comment: 5106)
R32  ValueDisplayed: 4.99k  [0603]  (hidden comment: CRCW06034K99FKEA)
R33  ValueDisplayed: 13.3k  [0603]  (hidden comment: CRCW060313K3FKEA)
R34  ValueDisplayed: 0  [0603]  (hidden comment: CRCW06030000Z0EA)
R35  ValueDisplayed: 6.98k  [0603]  (hidden comment: CRCW06036K98FKEA)
R36  ValueDisplayed: 14.3k  [0603]  (hidden comment: CRCW060314K3FKEA)
R37  ValueDisplayed: 51.1k  [0603]  (hidden comment: CRCW060351K1FKEA)
R38  ValueDisplayed: 23.7k  [0603]  (hidden comment: CRCW060323K7FKEA)
R39  ValueDisplayed: 4.99k  [0603]  (hidden comment: CRCW06034K99FKEA)
R40  ValueDisplayed: 10.0k  [0603]  (hidden comment: CRCW060310K0FKEA)
R41  ValueDisplayed: 12.7k  [0603]  (hidden comment: CRCW060312K7FKEA)
R42  ValueDisplayed: 10.2k  [0603]  (hidden comment: CRCW060310K2FKEA)
RESET  5000  [Keystone5000]  (value not drawn)
TP10  5000  [Keystone5000]  (value not drawn)
TP11  5000  [Keystone5000]  (value not drawn)
TP12  5000  [Keystone5000]  (value not drawn)
TP13  5000  [Keystone5000]  (value not drawn)
TP14  5000  [Keystone5000]  (value not drawn)
TP15  5000  [Keystone5000]  (value not drawn)
TP16  5001  [Keystone5001]  (value not drawn)
TP17  5000  [Keystone5000]  (value not drawn)
TP18  5001  [Keystone5001]  (value not drawn)
TP19  5000  [Keystone5000]  (value not drawn)
TP20  5000  [Keystone5000]  (value not drawn)
TP22  5001  [Keystone5001]  (value not drawn)
U4  TPS26624DRCR  [DRC0010J]
U5  TPS560430YDBVR  [DBV0006A_N]
U6  TPS2121RUXR  [RUX0012A]
U7  LP38691SD-3.3/NOPB  [NGG0006A_V]
U8  TPS22919DCKR  [DCK0006A_N]
U9  TPS3703A4330DSERQ1  [DSE0006A]

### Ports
PG_LM5164 (out), Reset (out), VCC_3.3V (in), VCC_3.3V (out), VCC_5V_BAT (in), VCC_5V_MAINS (in), VCC_5V_MAINS (out), VCC_5V_USB (in), VCC_15V (in), VCC_ENC1 (out), VCC_ENC2 (out)

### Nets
GND: C16.1 C17.2 C18.1 C19.2 C20.1 C21.1 C22.1 C25.1 C26.1 C27.1 C28.1 C29.2 C30.2 C31.1 C32.1 C33.1 C34.1 C35.1 C36.2 C37.1 C38.2 C39.1 C40.2 C41.2 C42.2 C43.2 R25.2 R32.2 R33.2 R34.2 R35.2 R37.2 R39.2 R41.2 R42.2 TP16.1 TP18.1 TP22.1 U4.6(GND) U5.2(GND) U6.12(GND) U7.2(GND) U7.7(DAP) U8.2(GND) U9.5(GND)
V_5VBAT: C36.1 C37.2 Q4.2(S) TP19.1 U8.1(IN) ; port VCC_5V_BAT
V_P: C30.1 C31.2 C40.1 C41.1 R40.2 TP15.1 U7.4(OUT) U7.5(SNS) U9.1(SENSE) U9.2(VDD) ; port VCC_3.3V
ON: Q4.3(D) R42.1 U8.3(ON)
OV1: R29.2 R32.1 U6.5(OV1)
PG_LM5164: Q4.1(G) R41.1 ; port PG_LM5164
PG_LM5164: U4.4(~{SHDN}) U5.4(~{SHDN})  [a separate net that carries the same name]
Reset: C42.1 R40.1 RESET.1 U9.4(~{RESET}) ; port Reset
VCC_5V_MAINS: C16.2 C17.1 C22.2 L2.2 R21.1 R23.1 R28.1 TP12.1 U4.1(IN) ; port VCC_5V_MAINS
VCC_5V_USB: C33.2 C34.2 C35.2 R36.2 R38.1 TP17.1 U6.2(IN2) ; port VCC_5V_USB
VCC_15V: R20.1 ; port VCC_15V
VCC_ENC1: C18.2 C19.1 R22.1 TP10.1 U4.10(OUT) ; port VCC_ENC1
VCC_ENC2: C38.1 C39.2 TP20.1 U8.5(QOD) U8.6(OUT) ; port VCC_ENC2
NetC15_1: C15.1 U5.1(CBOOT)
NetC15_2: C15.2 L2.1 TP11.1 U5.6(SW)
NetC20_2: C20.2 C21.2 R20.2 U5.5(VIN)
NetC23_1: C23.1 U4.8(DVDT)
NetC23_2: C23.2 R26.2 R27.2 U4.5(RTN) U4.11(PAD)
NetC25_2: C25.2 C26.2 C27.2 R28.2 R29.1 R30.1 U6.7(IN1)
NetC28_2: C28.2 C29.1 R31.2 U7.1(IN) U7.6(IN)
NetC32_2: C32.2 U6.11(SS)
NetC43_1: C43.1 U9.3(CT)
NetR21_2: R21.2 R24.1 U4.2(UVLO)
NetR22_2: R22.2 TP13.1 U4.9(~{FLT})
NetR23_2: R23.2 R25.1 U5.3(FB)
NetR24_2: R24.2 R26.1 U4.3(OVP)
NetR27_1: R27.1 U4.7(ILIM)
NetR30_2: R30.2 R33.1 U6.6(PR1)
NetR31_1: R31.1 TP14.1 U6.1(OUT) U6.8(OUT)
NetR34_1: R34.1 U6.9(ST)
NetR35_1: R35.1 R36.1 U6.3(CP2)
NetR37_1: R37.1 U6.10(ILM)
NetR38_2: R38.2 R39.1 U6.4(OV2)

Not connected (* = marked no-connect by the designer): U7 3(NC); U8 4(N/C); U9 6(~{MR})

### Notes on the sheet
- Labels drawn without touching a wire or pin: PG_LM5164

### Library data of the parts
C15 C17 C19 C21 C25-C27 C29 C30 C33-C36 C38 C40 C42 = CMP-0006753-4: CAP, CERM, 0.1 uF, 25 V, +/- 10%, X7R, 0603; Manufacturer: AVX; TaMin_C: -55°C; ESR_ohm: 0.05; Polarized: N; SizeAreaWB_mm2: 4.68; Value1: 0.05 ohm; U/M: EA; Value: 0.1uF; TaMax_C: 125°C; SizeZ_mm: 1; SizeX_mm: 1.6; SizeY_mm: 0.8; SizeArea_mm2: 1.28; AEC Category: Q200
C16 C31 C37 C39 = CMP-0007898-1: CAP, CERM, 1 uF, 16 V, +/- 10%, X8R, 0805; Manufacturer: TDK; TaMin_C: -55°C; Polarized: N; SizeAreaWB_mm2: 6.75; Value1: Unknown; U/M: EA; Value: 1uF; TaMax_C: 150°C; SizeZ_mm: 1.45; SizeX_mm: 2; SizeY_mm: 1.25; Cap_Case: 0805; SizeArea_mm2: 2.5; Cap_F: 1µF; AEC Category: Q200
C18 = CMP-0008378-2: CAP, CERM, 10 uF, 25 V, +/- 10%, X7R, 0805; Manufacturer: MuRata; TaMin_C: -55°C; Polarized: N; SizeAreaWB_mm2: 6.75; Value1: Unknown; U/M: EA; Value: 10uF; TaMax_C: 125°C; SizeZ_mm: 1.45; SizeX_mm: 2; SizeY_mm: 1.25; Cap_Case: 0805; SizeArea_mm2: 2.5; AEC Category: Q200
C20 C28 = CMP-0007885-2: CAP, CERM, 4.7 uF, 35 V, +/- 10%, X7R, 0805; Manufacturer: TDK; TaMin_C: -55°C; ESR_ohm: 2.346m; Polarized: N; SizeAreaWB_mm2: 6.75; Value1: 0.002346 ohm; U/M: EA; Value: 4.7uF; TaMax_C: 125°C; SizeZ_mm: 1.45; SizeX_mm: 2; SizeY_mm: 1.25; Cap_Case: 0805; SizeArea_mm2: 2.5; IRMS_A: 4.26021A; AEC Category: Q200
C22 = CMP-0009102-1: CAP, CERM, 15 uF, 16 V, +/- 20%, X5R, 1210; Manufacturer: TDK; TaMin_C: -55°C; ESR_ohm: 2.949m; Polarized: N; SizeAreaWB_mm2: 14.7; Value1: 0.002949 ohm; U/M: EA; Value: 15uF; TaMax_C: 85°C; SizeZ_mm: 2.8; SizeX_mm: 3.2; SizeY_mm: 2.5; SizeArea_mm2: 8; Cap_F: 15µF; IRMS_A: 4.28133A; AEC Category: Q200
C23 = CMP-0006900-4: CAP, CERM, 0.022 uF, 16 V, +/- 10%, X7R, 0603; Manufacturer: Kemet; TaMin_C: -55°C; Polarized: N; SizeAreaWB_mm2: 4.68; Value1: Unknown; U/M: EA; TaMax_C: 125°C; SizeZ_mm: 1; SizeX_mm: 1.6; SizeY_mm: 0.8; SizeArea_mm2: 1.28; AEC Category: Q200
C32 = CMP-0007730-2: CAP, CERM, 1 uF, 50 V, +/- 10%, X7R, 0805; Manufacturer: Kemet; TaMin_C: -55°C; Polarized: N; SizeAreaWB_mm2: 6.75; Value1: Unknown; U/M: EA; Value: 1uF; TaMax_C: 125°C; SizeZ_mm: 1.45; SizeX_mm: 2; SizeY_mm: 1.25; Cap_Case: 0805; SizeArea_mm2: 2.5; AEC Category: Q200
C41 = CMP-0007136-5: CAP, CERM, 1 uF, 16 V, +/- 10%, X7R, AEC-Q200 Grade 1, 0603; Manufacturer: MuRata; TaMin_C: -55°C; Polarized: N; SizeAreaWB_mm2: 4.68; Value1: Unknown; U/M: EA; Value: 1uF; TaMax_C: 125°C; SizeZ_mm: 1; SizeX_mm: 1.6; SizeY_mm: 0.8; SizeArea_mm2: 1.28; AEC Qualified: Y; AEC Category: Q200
C43 = CMP-0006922-4: CAP, CERM, 3300 pF, 50 V, +/- 10%, X7R, 0603; Manufacturer: Kemet; TaMin_C: -55°C; Polarized: N; SizeAreaWB_mm2: 4.68; Value1: Unknown; U/M: EA; Value: 3300pF; TaMax_C: 125°C; SizeZ_mm: 1; SizeX_mm: 1.6; SizeY_mm: 0.8; SizeArea_mm2: 1.28; AEC Category: Q200
L2 = CMP-0060543-1: Inductor, Drum Core, Ferrite, 6.8 uH, 1.1 A, 0.27 ohm, SMD; Manufacturer: Coilcraft; Isat: 1.2A @ 30% inductance drop; Irms: 1.1A @ 40C rise; Green_Lifecycle: Not Set; SizeAreaWB_mm2: 15.96; DCR_ohm: 0.27; Green_REACh: Incomplete; Value: 6.8uH; Imax_A: 1.1A; SizeZ_mm: 2; SizeX_mm: 3.2; SizeY_mm: 2.8; SizeArea_mm2: 8.96; Ind_H: 6.8µH; AEC Category: Q200
Q4 = CMP-0078322-2: MOSFET, P-CH, -20 V, -3.6 A, YJN0003A (PICOSTAR-3); Manufacturer: Texas Instruments; Alternate Manufacturer: None; SizeArea_mm2: 0.414; VdsMax_V: -20V; QgTyp_nC: 1.02; Value1: 0.076 ohm; AEC Category: Q101; SizeX_mm: 0.69; IdsMax_A: -3.6A; Value: -20V; Rdson45_ohm: 0.076; Value2: 1.02 nC; SizeAreaWB_mm2: 2.704; SizeZ_mm: 0.22; SizeY_mm: 0.6; ChType: P; AEC Qualified: N; ChMode: Enhancement
R20 R28 R31 = CMP-0020833-2: as R13 on sheet TIDA_010070_Sheet1_09
R21 = CMP-0022237-4: RES, 24.9 k, 1%, 0.1 W, AEC-Q200 Grade 0, 0603; Manufacturer: Vishay-Dale; Power_W: 100mW; TempCo: 100 ppm/C; Value_Code: 24k9; Value: 24.9k; EIA_Code: E96; SizeX_mm: 1.6; SizeY_mm: 0.8; SizeZ_mm: 1; Value2: 0.1W; SizeArea_mm2: 1.28; AEC Qualified: Y; VDC_V: 75V; AEC Category: Q200; AEC Grade: 0
R22 = CMP-0022447-4: RES, 49.9 k, 1%, 0.1 W, AEC-Q200 Grade 0, 0603; Manufacturer: Vishay-Dale; Power_W: 100mW; TempCo: 100 ppm/C; Value_Code: 49k9; Value: 49.9k; EIA_Code: E96; SizeX_mm: 1.6; SizeY_mm: 0.8; SizeZ_mm: 1; Value2: 0.1W; SizeArea_mm2: 1.28; AEC Qualified: Y; VDC_V: 75V; AEC Category: Q200; AEC Grade: 0
R23 = CMP-0022632-4: RES, 88.7 k, 1%, 0.1 W, AEC-Q200 Grade 0, 0603; Manufacturer: Vishay-Dale; Power_W: 100mW; TempCo: 100 ppm/C; Value_Code: 88k7; Value: 88.7k; EIA_Code: E96; SizeX_mm: 1.6; SizeY_mm: 0.8; SizeZ_mm: 1; Value2: 0.1W; SizeArea_mm2: 1.28; AEC Qualified: Y; VDC_V: 75V; AEC Category: Q200; AEC Grade: 0
R24 = CMP-0022123-4: RES, 1.40 k, 1%, 0.1 W, AEC-Q200 Grade 0, 0603; Manufacturer: Vishay-Dale; Power_W: 100mW; TempCo: 100 ppm/C; Value_Code: 1k40; Value: 1.40k; EIA_Code: E96; Res_ohm: 1.4k; SizeX_mm: 1.6; SizeY_mm: 0.8; SizeZ_mm: 1; Value2: 0.1W; SizeArea_mm2: 1.28; AEC Qualified: Y; VDC_V: 75V; AEC Category: Q200; AEC Grade: 0
R25 = CMP-0022220-4: RES, 22.1 k, 1%, 0.1 W, AEC-Q200 Grade 0, 0603; Manufacturer: Vishay-Dale; Power_W: 100mW; TempCo: 100 ppm/C; Value_Code: 22k1; Value: 22.1k; EIA_Code: E96; SizeX_mm: 1.6; SizeY_mm: 0.8; SizeZ_mm: 1; Value2: 0.1W; SizeArea_mm2: 1.28; AEC Qualified: Y; VDC_V: 75V; AEC Category: Q200; AEC Grade: 0
R26 = CMP-0022634-4: RES, 8.06 k, 1%, 0.1 W, AEC-Q200 Grade 0, 0603; Manufacturer: Vishay-Dale; Power_W: 100mW; TempCo: 100 ppm/C; Value_Code: 8k06; Value: 8.06k; EIA_Code: E96; SizeX_mm: 1.6; SizeY_mm: 0.8; SizeZ_mm: 1; Value2: 0.1W; SizeArea_mm2: 1.28; AEC Qualified: Y; VDC_V: 75V; AEC Category: Q200; AEC Grade: 0
R27 = CMP-0022249-4: RES, 26.7 k, 1%, 0.1 W, AEC-Q200 Grade 0, 0603; Manufacturer: Vishay-Dale; Power_W: 100mW; TempCo: 100 ppm/C; Value_Code: 26k7; Value: 26.7k; EIA_Code: E96; SizeX_mm: 1.6; SizeY_mm: 0.8; SizeZ_mm: 1; Value2: 0.1W; SizeArea_mm2: 1.28; AEC Qualified: Y; VDC_V: 75V; AEC Category: Q200; AEC Grade: 0
R29 R38 = CMP-0022229-4: RES, 23.7 k, 1%, 0.1 W, AEC-Q200 Grade 0, 0603; Manufacturer: Vishay-Dale; Power_W: 100mW; TempCo: 100 ppm/C; Value_Code: 23k7; Value: 23.7k; EIA_Code: E96; SizeX_mm: 1.6; SizeY_mm: 0.8; SizeZ_mm: 1; Value2: 0.1W; SizeArea_mm2: 1.28; AEC Qualified: Y; VDC_V: 75V; AEC Category: Q200; AEC Grade: 0
R30 = CMP-0022228-4: RES, 23.2 k, 1%, 0.1 W, AEC-Q200 Grade 0, 0603; Manufacturer: Vishay-Dale; Power_W: 100mW; TempCo: 100 ppm/C; Value_Code: 23k2; Value: 23.2k; EIA_Code: E96; SizeX_mm: 1.6; SizeY_mm: 0.8; SizeZ_mm: 1; Value2: 0.1W; SizeArea_mm2: 1.28; AEC Qualified: Y; VDC_V: 75V; AEC Category: Q200; AEC Grade: 0
R32 R39 = CMP-0022458-4: RES, 4.99 k, 1%, 0.1 W, AEC-Q200 Grade 0, 0603; Manufacturer: Vishay-Dale; Power_W: 100mW; TempCo: 100 ppm/C; Value_Code: 4k99; Value: 4.99k; EIA_Code: E96; SizeX_mm: 1.6; SizeY_mm: 0.8; SizeZ_mm: 1; Value2: 0.1W; SizeArea_mm2: 1.28; AEC Qualified: Y; VDC_V: 75V; AEC Category: Q200; AEC Grade: 0
R33 = CMP-0022043-4: RES, 13.3 k, 1%, 0.1 W, AEC-Q200 Grade 0, 0603; Manufacturer: Vishay-Dale; Power_W: 100mW; TempCo: 100 ppm/C; Value_Code: 13k3; Value: 13.3k; EIA_Code: E96; SizeX_mm: 1.6; SizeY_mm: 0.8; SizeZ_mm: 1; Value2: 0.1W; SizeArea_mm2: 1.28; AEC Qualified: Y; VDC_V: 75V; AEC Category: Q200; AEC Grade: 0
R34 = CMP-0025697-4: RES, 0, 5%, 0.1 W, AEC-Q200 Grade 0, 0603; Manufacturer: Vishay-Dale; Power_W: 100mW; TempCo: 200 ppm/C; Value_Code: 0000; Value: 0; EIA_Code: E24; SizeX_mm: 1.6; SizeY_mm: 0.8; SizeZ_mm: 1; Value2: 0.1W; SizeArea_mm2: 1.28; AEC Qualified: Y; VDC_V: 75V; AEC Category: Q200
R35 = CMP-0022564-4: RES, 6.98 k, 1%, 0.1 W, AEC-Q200 Grade 0, 0603; Manufacturer: Vishay-Dale; Power_W: 100mW; TempCo: 100 ppm/C; Value_Code: 6k98; Value: 6.98k; EIA_Code: E96; SizeX_mm: 1.6; SizeY_mm: 0.8; SizeZ_mm: 1; Value2: 0.1W; SizeArea_mm2: 1.28; AEC Qualified: Y; VDC_V: 75V; AEC Category: Q200; AEC Grade: 0
R36 = CMP-0022055-4: RES, 14.3 k, 1%, 0.1 W, AEC-Q200 Grade 0, 0603; Manufacturer: Vishay-Dale; Power_W: 100mW; TempCo: 100 ppm/C; Value_Code: 14k3; Value: 14.3k; EIA_Code: E96; SizeX_mm: 1.6; SizeY_mm: 0.8; SizeZ_mm: 1; Value2: 0.1W; SizeArea_mm2: 1.28; AEC Qualified: Y; VDC_V: 75V; AEC Category: Q200; AEC Grade: 0
R37 = CMP-0022482-4: RES, 51.1 k, 1%, 0.1 W, AEC-Q200 Grade 0, 0603; Manufacturer: Vishay-Dale; Power_W: 100mW; TempCo: 100 ppm/C; Value_Code: 51k1; Value: 51.1k; EIA_Code: E96; SizeX_mm: 1.6; SizeY_mm: 0.8; SizeZ_mm: 1; Value2: 0.1W; SizeArea_mm2: 1.28; AEC Qualified: Y; VDC_V: 75V; AEC Category: Q200; AEC Grade: 0
R40 = CMP-0021998-4: RES, 10.0 k, 1%, 0.1 W, AEC-Q200 Grade 0, 0603; Manufacturer: Vishay-Dale; Power_W: 100mW; TempCo: 100 ppm/C; Value_Code: 10k0; Value: 10.0k; EIA_Code: E96; Res_ohm: 10k; SizeX_mm: 1.6; SizeY_mm: 0.8; SizeZ_mm: 1; Value2: 0.1W; SizeArea_mm2: 1.28; AEC Qualified: Y; VDC_V: 75V; AEC Category: Q200; AEC Grade: 0
R41 = CMP-0022032-4: RES, 12.7 k, 1%, 0.1 W, AEC-Q200 Grade 0, 0603; Manufacturer: Vishay-Dale; Power_W: 100mW; TempCo: 100 ppm/C; Value_Code: 12k7; Value: 12.7k; EIA_Code: E96; SizeX_mm: 1.6; SizeY_mm: 0.8; SizeZ_mm: 1; Value2: 0.1W; SizeArea_mm2: 1.28; AEC Qualified: Y; VDC_V: 75V; AEC Category: Q200; AEC Grade: 0
R42 = CMP-0021999-4: RES, 10.2 k, 1%, 0.1 W, AEC-Q200 Grade 0, 0603; Manufacturer: Vishay-Dale; Power_W: 100mW; TempCo: 100 ppm/C; Value_Code: 10k2; Value: 10.2k; EIA_Code: E96; SizeX_mm: 1.6; SizeY_mm: 0.8; SizeZ_mm: 1; Value2: 0.1W; SizeArea_mm2: 1.28; AEC Qualified: Y; VDC_V: 75V; AEC Category: Q200; AEC Grade: 0
RESET TP10-TP15 TP17 TP19 TP20 = CMP-0055137-1: as TP1 on sheet TIDA_010070_Sheet1_09
TP16 TP18 TP22 = CMP-0055138-1: as TP4 on sheet TIDA_010070_Sheet1_09
U4 = CMP-0013390-7: 60-V, 800-mA Industrial eFuse with Integrated Reverse Polarity Protection, DRC0010J (VSON-10); Alternate PartNumber: TPS26624DRCT; Alternate Manufacturer: Texas Instruments; SizeArea_mm2: 9; AEC Category: Q200; SizeAreaWB_mm2: 16; Rating: Catalog; SizeY_mm: 3; SizeZ_mm: 1; AEC Qualified: N; CompType: IC
U5 = CMP-0065101-2: 4V to 36 V 0.6 A Synchronous Step-Down Converter, DBV0006A (SOT-23-6); Manufacturer: Texas Instruments; Alternate PartNumber: TPS560430YDBVT; SizeX_mm: 2.8; SizeY_mm: 2.9; CompType: IC; SizeZ_mm: 1.45; SizeArea_mm2: 8.12; SizeAreaWB_mm2: 14.82; U/M: EA
U6 = CMP-0078351-3: 2.7V-22V, 4A, 50mohm Priority Power MUX, RUX0012A (VQFN-HR-12); Alternate PartNumber: TPS2121RUXT; Alternate Manufacturer: Texas Instruments; SizeAreaWB_mm2: 10.5; SizeZ_mm: 1; SizeX_mm: 2; SizeY_mm: 2.5; SizeArea_mm2: 5; CompType: IC; AEC Qualified: N; AEC Category: Q200
U7 = CMP-0070735-1: 500mA Low Dropout CMOS Linear Regulators Stable with Ceramic Output Capacitors, 6-pin LLP, Pb-Free, 1000 Reel; Manufacturer: Texas Instruments; CompType: LDO IC; PackageTopMarking: ZXYTT*L120B; High-Reliability: Y
U8 = CMP-0081108-1: 5.5-V, 1.5-A, 100-mohm Load Switch with Output Discharge, DCK0006A (SOT-SC70-6); Alternate PartNumber: TPS22919DCKT; Alternate Manufacturer: Texas Instruments; SizeAreaWB_mm2: 9.3; SizeZ_mm: 1.1; SizeX_mm: 2.1; SizeY_mm: 2; SizeArea_mm2: 4.2; CompType: IC; AEC Qualified: N; AEC Category: Q200
U9 = CMP-0750051-1: Overvoltage and Undervoltage Reset IC With Time Delay and Manual Reset, DSE0006A (WSON-6); Alternate Manufacturer: Texas Instruments; AEC Category: Q200; SizeY_mm: 1.5; AEC Qualified: Y; SizeAreaWB_mm2: 6.25; SizeZ_mm: 0.8; SizeArea_mm2: 2.25

## Sheet TIDA_010070_Hardware.SchDoc
size 431 x 279 mm; Date: Not shown in title block; ApprovedBy: Not shown in title block; CheckedBy: Not shown in title block; Author: Not shown in title block; CompanyName: Not shown in title block; Engineer: Not shown in title block; Organization: Not shown in title block; Address1: Not shown in title block; Address2: Not shown in title block; Address3: Not shown in title block; Address4: Not shown in title block; DocumentNumber: 3; Revision: Use project parameter SCH_Rev; SheetNumber: 3; SheetTotal: 3; PageSetup: Record=PageOptions¦CenterHorizontal=True¦CenterVertical=True¦PrintScale=1.00¦XCorrection=1.00¦YCorrection=1.00¦PrintKind=0¦BorderSize=5000000¦LeftOffset=0¦BottomOffset=0¦Orientation=2¦PaperLength=1000¦PaperWidth=1000¦Scale=100¦PaperSource=15¦PrintQuality=600¦MediaType=1¦DitherType=10¦PaperKind=Letter¦PrintScaleMode=1
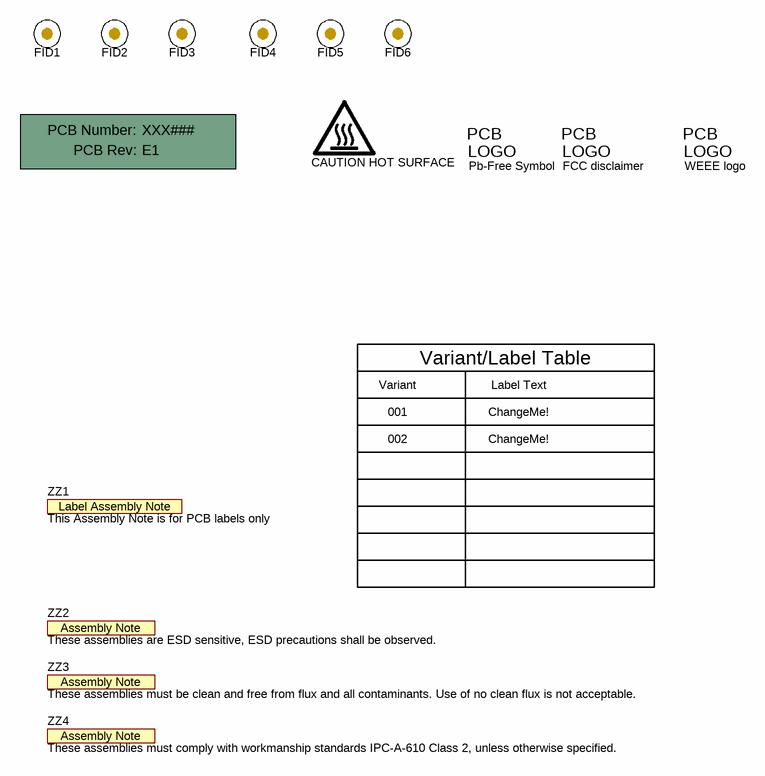
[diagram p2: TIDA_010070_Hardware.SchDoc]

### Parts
!PCB1  Printed Circuit Board  (value not drawn)  (mechanical)
FID1  Fiducial  [Fiducial10-20]  (value not drawn)
FID2  Fiducial  [Fiducial10-20]  (value not drawn)
FID3  Fiducial  [Fiducial10-20]  (value not drawn)
FID4  Fiducial  [Fiducial10-20]  (value not drawn)
FID5  Fiducial  [Fiducial10-20]  (value not drawn)
FID6  Fiducial  [Fiducial10-20]  (value not drawn)
LOGO1  CAUTION HOT SURFACE  [IEC_HotSurface_Small]  (no BOM)
Logo2  Pb-Free Symbol  [Pb-Free_Overlay_Small]  (no BOM)
Logo3  FCC disclaimer  [FCC_disclaimer]  (no BOM)
Logo4  WEEE logo  [WEEE_Minimum]  (no BOM)
ZZ1  This Assembly Note is for PCB labels only  [AssemblyNoteLabel]  (no BOM)
ZZ2  These assemblies are ESD sensitive, ESD precautions shall be observed.  [AssemblyNote]  (no BOM)
ZZ3  These assemblies must be clean and free from flux and all contaminants. Use of no clean flux is not acceptable.  [AssemblyNote]  (no BOM)
ZZ4  These assemblies must comply with workmanship standards IPC-A-610 Class 2, unless otherwise specified.  [AssemblyNote]  (no BOM)

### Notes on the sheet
- Variant
- Variant/Label Table
- Label Text
- 001
- 002
- ChangeMe!

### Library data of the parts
!PCB1 = CMP-0003618-2: Manufacturer: Any; PartNumber: XXX###
FID1-FID6 = CMP-0077181-1: Fiducial mark.  There is nothing to buy or mount.
LOGO1 = CMP-0074837-1: IEC 61010-1 Hot Surface Warning; Library Reference: IEC_HotSurface; SymbolCreator: a0412235
Logo2 = CMP-0074839-1: Library Reference: Logo; SymbolCreator: a0412235
Logo3 = CMP-0074847-1: FCC_disclaimer; Library Reference: Logo
Logo4 = CMP-0074769-1
ZZ1 = CMP-0003616-3
ZZ2 = CMP-0077236-1
ZZ3 = CMP-0077237-1
ZZ4 = CMP-0077238-1

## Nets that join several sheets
GND: TIDA_010070_Sheet1_09 (36 pins), TIDA_010070_Sheet2_09 (45 pins)
V_5VBAT: TIDA_010070_Sheet1_09 (J6.1), TIDA_010070_Sheet2_09 (5 pins)
V_P: TIDA_010070_Sheet1_09 (J8.1), TIDA_010070_Sheet2_09 (10 pins)
PG_LM5164: TIDA_010070_Sheet1_09 (R12.1 U3.6), TIDA_010070_Sheet2_09 (Q4.1 R41.1)
VCC_15V: TIDA_010070_Sheet1_09 (7 pins), TIDA_010070_Sheet2_09 (R20.1)
VCC_ENC1: TIDA_010070_Sheet1_09 (J1.1), TIDA_010070_Sheet2_09 (5 pins)
VCC_ENC2: TIDA_010070_Sheet1_09 (J4.1), TIDA_010070_Sheet2_09 (5 pins)

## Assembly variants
001: not fitted D2 FID1 FID2 FID3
